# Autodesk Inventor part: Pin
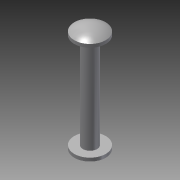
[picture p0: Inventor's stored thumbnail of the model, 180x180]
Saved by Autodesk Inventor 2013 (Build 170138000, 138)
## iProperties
Created: 2009-03
Part Number: Pin
Material: Steel
Document SubType Name: Modeling
Designer: tangg
Density: 7.85 g/cm^3
Author: tangg
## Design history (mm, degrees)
sketch "Sketch1"
  geometry: C1 r 1.5 at (0, 0); 1 further point
  constraints: 1 centre point, 1 coincident
  dimensions: "d0" = 3 diameter of C1
extrude "Extrusion1" new body sketch "Sketch1" stored distance "d1" = 20; taper "d2" = 0 deg
sketch "Sketch2"
  geometry: L1 (1.5, -10)-(-1.5, -10) reference; L2 (0, -11.82)-(0, -10); L3 (-3.289, -10)-(0, -10); L4 (-3.289, -10)-(-3.289, -10.695); A1 r 5.373 centre (0, -6.447) between (-3.289, -10.695) and (0, -11.82); 1 further point
  constraints: 6 end point, 2 point on circle, 1 centre point, 1 collinear, 1 midpoint, 1 perpendicular
revolve "Revolution1" sketch "Sketch2" stored, may be unused: angle "d3" = 90 deg
mirror "Mirror1"
body "Solid1"
